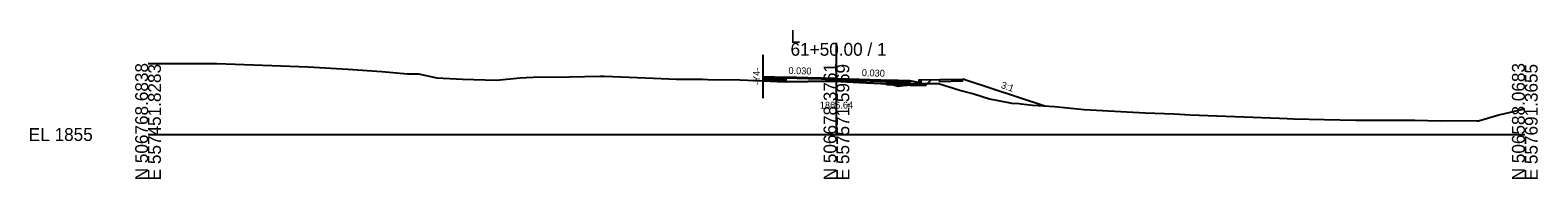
# Model space of a CAD drawing. Extents: x -26 to 4603, y -10 to 4703.
# Drawn here: x 2474.3 to 2802.8, y 655.3 to 687.8 of the extents above; entities that cross this region are included whole.
import ezdxf

# ---------------------------------------------------------------- set-up
doc = ezdxf.new("R2010")
doc.units = 0
for name, color, linetype in [('Default', 7, 'Continuous'), ('Exist Cross Section Cell', 7, 'Continuous'), ('Exist XS Ground Line', 7, 'Continuous'), ('Prop CMT Pvmt Course 1', 7, 'Continuous'), ('Prop CMT Pvmt Course 2', 7, 'Continuous'), ('Prop CMT Pvmt Course 3', 7, 'Continuous'), ('Prop CMT Pvmt Milling', 7, 'Continuous'), ('Prop CMT Shear Line', 7, 'Continuous'), ('Prop CMT Shld Paved Course 2', 7, 'Continuous'), ('Prop CMT Subgrade Earthwork', 7, 'Continuous'), ('Prop Conc 4in Sidewalk', 7, 'Continuous'), ('Prop Conc Curb and Gutter', 7, 'Continuous'), ('Prop Corridor Mesh Bottom', 7, 'Continuous'), ('Prop XS Finish Grade', 7, 'Continuous'), ('Prop XS Label Text', 7, 'Continuous'), ('Prop XS Shear Point Element', 7, 'Continuous'), ('Prop XS Shear Point Label', 7, 'Continuous'), ('Prop XS SS Elevation Text', 7, 'Continuous')]:
    doc.layers.add(name, color=color, linetype=linetype)

msp = doc.modelspace()

# ---------------------------------------------------------------- linework, layer by layer
at = {"layer": 'Exist Cross Section Cell'}
for p, q in [((2650, 665), (2650, 685)), ((2500, 665), (2650, 665)), ((2650, 665), (2800, 665))]:
    msp.add_line(p, q, dxfattribs=at)
at = {"layer": 'Exist XS Ground Line'}
msp.add_lwpolyline([(2500, 680.47), (2508.3, 680.49), (2511.73, 680.49), (2514.99, 680.47), (2522.94, 680.19), (2534.88, 679.75), (2538.57, 679.57), (2543.51, 679.28), (2550.92, 678.74), (2556.55, 678.28), (2558.94, 678.23), (2562.91, 677.41), (2568.54, 677.12), (2575.96, 676.86), (2581.06, 677.34), (2582.37, 677.44), (2583.95, 677.49), (2591.77, 677.63), (2598.54, 677.76), (2599.45, 677.76), (2610.13, 677.27), (2615.16, 677.05), (2615.17, 677.05), (2615.17, 677.05), (2615.17, 677.05), (2616.72, 677.05), (2617.38, 677.07), (2618.46, 677.06), (2620.61, 677.06), (2620.82, 677.05), (2622, 677.03), (2628.98, 676.91), (2638.85, 676.52), (2643.85, 676.59), (2649.68, 676.65), (2654.95, 676.38), (2659.66, 676.16), (2660.71, 676.1), (2661.39, 676.06), (2662.37, 675.82), (2663.48, 675.57), (2664.57, 675.68), (2665.42, 675.76), (2667.18, 675.97), (2668.32, 676.16), (2670.6, 676.15), (2672.26, 676.13), (2675.54, 675.09), (2677.13, 674.64), (2679.91, 673.86), (2683.32, 672.82), (2687.82, 671.93), (2688.14, 671.88), (2689.8, 671.77), (2690.24, 671.7), (2692.72, 671.41), (2697.51, 671.1), (2703.95, 670.46), (2717.27, 669.76), (2723.62, 669.49), (2727.07, 669.33), (2746.51, 668.55), (2748.24, 668.49), (2749.57, 668.43), (2763.11, 668.16), (2776.06, 668.1), (2781.61, 668), (2784.53, 668.03), (2789.51, 668.02), (2789.88, 668.01), (2794.37, 669.27), (2794.99, 669.44), (2795.38, 669.54), (2799, 670.41), (2799.24, 670.44), (2800, 670.56)], dxfattribs=at)
at = {"layer": 'Prop CMT Pvmt Course 1'}
for points in [[(2634, 677.7), (2639, 677.55), (2639, 677.55), (2639, 677.3), (2634, 677.45), (2634, 677.45), (2634, 677.7), (2634, 677.7), (2634, 677.7)], [(2649.68, 677.23), (2649.67, 677.23), (2643.85, 677.41), (2643.85, 677.41), (2639, 677.55), (2639, 677.55), (2639, 676.52), (2643.85, 676.59), (2643.85, 676.59), (2649.67, 676.65), (2649.68, 676.65), (2649.68, 676.65), (2650, 676.64), (2650, 677.22), (2650, 677.22), (2649.68, 677.23), (2649.68, 677.23)], [(2661, 676.89), (2661, 676.89), (2661, 676.89), (2661, 676.08), (2661, 676.08), (2660.71, 676.1), (2660.71, 676.1), (2659.66, 676.16), (2659.65, 676.16), (2654.95, 676.38), (2654.95, 676.38), (2650, 676.64), (2650, 677.22), (2650, 677.22), (2654.95, 677.07), (2654.95, 677.07), (2659.65, 676.93), (2659.66, 676.93), (2660.71, 676.9), (2660.71, 676.9), (2661, 676.89)], [(2661, 676.89), (2661, 676.89), (2661, 676.89), (2661, 676.64), (2661, 676.64), (2665.99, 676.49), (2665.99, 676.74), (2665.99, 676.74), (2661, 676.89)]]:
    msp.add_lwpolyline(points, dxfattribs=at)
at = {"layer": 'Prop CMT Pvmt Course 2'}
for points in [[(2634, 677.45), (2639, 677.3), (2639, 677.3), (2639, 676.97), (2634, 677.12), (2634, 677.12), (2634, 677.45), (2634, 677.45), (2634, 677.45)], [(2661, 676.64), (2661, 676.64), (2661, 676.64), (2661, 676.31), (2661, 676.31), (2665.99, 676.16), (2665.99, 676.49), (2665.99, 676.49), (2661, 676.64)]]:
    msp.add_lwpolyline(points, dxfattribs=at)
at = {"layer": 'Prop CMT Pvmt Course 3'}
for points in [[(2634, 677.12), (2639, 676.97), (2639, 676.97), (2639, 676.59), (2634, 676.74), (2634, 676.74), (2634, 677.12), (2634, 677.12), (2634, 677.12)], [(2661, 676.31), (2661, 676.31), (2661, 676.31), (2661, 675.93), (2661, 675.93), (2665.99, 675.78), (2665.99, 676.16), (2665.99, 676.16), (2661, 676.31)], [(2665.99, 676.16), (2665.99, 676.16), (2665.99, 676.16), (2665.99, 675.78), (2665.99, 675.78), (2669.38, 675.68), (2668.99, 676.07), (2668.99, 676.07), (2665.99, 676.16)]]:
    msp.add_lwpolyline(points, dxfattribs=at)
at = {"layer": 'Prop CMT Pvmt Milling'}
for points in [[(2650, 676.64), (2649.68, 676.65), (2649.68, 676.65), (2649.67, 676.65), (2643.85, 676.59), (2643.85, 676.59), (2639, 676.52)], [(2650, 676.64), (2654.95, 676.38), (2654.95, 676.38), (2659.65, 676.16), (2659.66, 676.16), (2660.71, 676.1), (2660.71, 676.1), (2661, 676.08), (2661, 676.08)]]:
    msp.add_lwpolyline(points, dxfattribs=at)
at = {"layer": 'Prop CMT Shld Paved Course 2'}
for points in [[(2649.68, 676.98), (2649.67, 676.98), (2643.85, 677.16), (2643.85, 677.16), (2639, 677.3), (2639, 677.3), (2639, 676.52), (2643.85, 676.59), (2643.85, 676.59), (2649.52, 676.65), (2649.52, 676.65), (2649.68, 676.65), (2649.68, 676.65), (2649.68, 676.65), (2649.95, 676.64), (2649.95, 676.64), (2650, 676.64), (2650, 676.97), (2650, 676.97), (2649.68, 676.98), (2649.68, 676.98)], [(2661, 676.64), (2661, 676.64), (2661, 676.64), (2661, 676.08), (2661, 676.08), (2660.71, 676.1), (2660.71, 676.1), (2659.66, 676.16), (2659.65, 676.16), (2654.95, 676.38), (2654.95, 676.38), (2650, 676.64), (2650, 676.97), (2650, 676.97), (2654.95, 676.82), (2654.95, 676.82), (2659.65, 676.68), (2659.66, 676.68), (2660.71, 676.65), (2660.71, 676.65), (2661, 676.64)]]:
    msp.add_lwpolyline(points, dxfattribs=at)
at = {"layer": 'Prop CMT Subgrade Earthwork'}
for points in [[(2670.58, 676.88), (2670.58, 676.88), (2669.38, 675.68)], [(2634, 676.74), (2639, 676.59)], [(2669.38, 675.68), (2661, 675.93), (2661, 675.93)]]:
    msp.add_lwpolyline(points, dxfattribs=at)
at = {"layer": 'Prop Conc 4in Sidewalk'}
msp.add_lwpolyline([(2677.49, 677.02), (2672.49, 676.92), (2672.49, 676.92), (2672.48, 676.59), (2677.5, 676.69), (2677.5, 676.69), (2677.49, 677.02), (2677.49, 677.02), (2677.49, 677.02)], dxfattribs=at)
at = {"layer": 'Prop Conc Curb and Gutter'}
msp.add_lwpolyline([(2665.99, 676.74), (2665.99, 676.74), (2665.99, 676.74), (2665.99, 676.16), (2665.99, 676.16), (2668.49, 676.08), (2668.49, 676.84), (2668.49, 676.84), (2667.99, 676.84), (2667.99, 676.84), (2667.99, 676.84), (2667.99, 676.34), (2665.99, 676.74)], dxfattribs=at)
at = {"layer": 'Prop Corridor Mesh Bottom'}
msp.add_lwpolyline([(2665.99, 676.74), (2665.99, 676.49)], dxfattribs=at)
at = {"layer": 'Prop XS Finish Grade'}
for points in [[(2672.49, 676.92), (2672.49, 676.92), (2668.49, 676.84)], [(2677.99, 677.03), (2677.99, 677.03), (2677.49, 677.02)], [(2677.99, 677.03), (2695.38, 671.24)]]:
    msp.add_lwpolyline(points, dxfattribs=at)
at = {"layer": 'Prop XS Shear Point Element'}
msp.add_line((2634, 672.94), (2634, 682.43), dxfattribs=at)

# ---------------------------------------------------------------- texts
at = {"layer": 'Default'}
msp.add_text('-', height=0.0001, dxfattribs=at).set_placement((2500, 665))
at = {"layer": 'Exist Cross Section Cell'}
for s, p in [('L', (2640, 685)), ('61+50.00 / 1', (2640, 682.2)), ('EL 1855', (2474, 663.6))]:
    msp.add_text(s, height=2.8, dxfattribs=at).set_placement(p)
for s, p in [('N 506768.6838', (2500, 655)), ('E 557451.8283', (2502.8, 655)), ('N 506678.3761', (2650, 655)), ('E 557571.5969', (2652.8, 655)), ('N 506588.0683', (2800, 655)), ('E 557691.3655', (2802.8, 655))]:
    msp.add_text(s, height=2.8, rotation=90, dxfattribs=at).set_placement(p)
at = {"layer": 'Prop CMT Shear Line'}
for p in [(2634, 677.7), (2650, 677.22), (2672.49, 676.92), (2677.49, 677.02), (2677.99, 677.03), (2665.99, 676.74), (2665.99, 676.74), (2667.99, 676.34), (2695.38, 671.24)]:
    msp.add_text('X', height=0.0025, dxfattribs=at).set_placement(p)
at = {"layer": 'Prop XS Label Text'}
for s, rotation, p in [('0.030', 358.2816, (2639.52, 678.24)), ('0.030', 358.2816, (2655.51, 677.76)), ('3:1', 341.5668, (2685.74, 675.19))]:
    msp.add_text(s, height=1.5, rotation=rotation, dxfattribs=at).set_placement(p)
at = {"layer": 'Prop XS Shear Point Label'}
msp.add_text('-Y4-', height=1.5, rotation=90, dxfattribs=at).set_placement((2633.33, 675.8))
at = {"layer": 'Prop XS SS Elevation Text'}
msp.add_text('1866.64', height=1.5, dxfattribs=at).set_placement((2646.38, 670.66))

doc.saveas('drawing.dxf')
